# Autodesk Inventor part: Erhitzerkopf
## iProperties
Created: 2003-12
Part Number: Erhitzerkopf
Material: Stahl (schweißbar)
Document SubType Name: Modellieren
Designer: Ulrich
Control State: 0
Master: False
Checked Out: False
Shininess: 20.0
Angle Display Precision: 2
Document Length Units: 11269
Document Angle Units: 11279
Document Time Units: 11290
Document Mass Units: 11283
Document Length Units Precision: 3
Document Angle Units Precision: 2
Density: 0.0
Volumn: 0.0
Area: 0.0
PropertySet Name: Model Information
Author: Ulrich
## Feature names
1. Zylinder_Gewinde [Extrusion]
2. Zylinder_Außen [Extrusion]
3. Zylinder_Innen [Extrusion]
